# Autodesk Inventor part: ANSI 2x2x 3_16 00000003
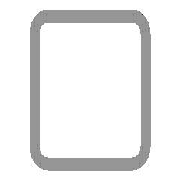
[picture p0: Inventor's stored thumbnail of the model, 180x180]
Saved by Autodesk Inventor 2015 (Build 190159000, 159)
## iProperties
_FrameMemberDoc: Frame Member File
_Version: 15.0.0
_CCFamilyMember: 1
_CCFamilyDisplayName: ANSI AISC (Square) - Tube
Created: 2007-02
Part Number: ANSI 2x2x 3_16 00000003
Material: Steel
Document SubType Name: Modeling
Standard: AISC
Designer: Autodesk, Inc.
Size Designation: 2x2x3/16
Stock Number: 2x2x 3/16
Density: 7.85 g/cm^3
Description: Tube
Standards Organization: ANSI
Language: en-US
Categories: <MemberInstance><Categories><Category DisplayName="Structural Shapes" InternalName="089c4875-fa83-4c05-b084-43b9cc11f5ed" Mnemonic="GRDR"><CategoryParameter Dis
Mass: 3346.04 g
Surface Area: 1806.39 cm^2
Volume: 426.248 cm^3
Appearance: Steel
IsCustomPart: 1
G_L: 20.500 in
G_W: 2.000 in
G_H: 2.000 in
+D0CDFDCA-4112-49B6-A064-F741B9AF15A3+CUTDETAIL1: Cut
+A485B58D-E367-4ED6-8CC1-ECB7B964D423+CUTDETAIL2: Cut
Author: Autodesk, Inc.
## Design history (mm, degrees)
node "Start plane"
node "End plane"
sketch "Sketch"
  geometry: L1 (-25.4, -15.875)-(-25.4, 15.875); L2 (-15.875, 25.4)-(15.875, 25.4); L3 (25.4, 15.875)-(25.4, -15.875); L4 (15.875, -25.4)-(-15.875, -25.4); L5 (-15.875, 20.637)-(15.875, 20.638); L6 (20.637, 15.875)-(20.637, -15.875); L7 (15.875, -20.637)-(-15.875, -20.638); L8 (-20.637, -15.875)-(-20.637, 15.875); L9 (0, 38.322)-(0, -38.322) reference; L10 (-38.322, 0)-(38.322, 0) reference; A1 r 9.525 centre (-15.875, -15.875) between (-25.4, -15.875) and (-15.875, -25.4); A2 r 9.525 centre (-15.875, 15.875) between (-15.875, 25.4) and (-25.4, 15.875); A3 r 9.525 centre (15.875, 15.875) between (25.4, 15.875) and (15.875, 25.4); A4 r 9.525 centre (15.875, -15.875) between (15.875, -25.4) and (25.4, -15.875); A5 r 4.762 centre (-15.875, 15.875) between (-15.875, 20.637) and (-20.637, 15.875); A6 r 4.762 centre (15.875, 15.875) between (20.637, 15.875) and (15.875, 20.638); A7 r 4.762 centre (15.875, -15.875) between (15.875, -20.637) and (20.637, -15.875); A8 r 4.762 centre (-15.875, -15.875) between (-20.637, -15.875) and (-15.875, -20.638)
  constraints: 16 end point, 16 point on circle, 8 centre point, 8 tangent, 4 parallel, 3 equal radius, 2 perpendicular, 7 other
  dimensions: "d10" = 50.8 distance between parallel lines of L2 L4 (= G_H); "d11" = 50.8 distance between parallel lines of L1 L3 (= G_W); "d12" = 4.7625 distance between parallel lines of L3 L6 (= G_T); "d15" = 25.4 distance between parallel lines of L2 L10 (= 0.5 x d10); "d16" = 25.4 distance between parallel lines of L9 L3 (= 0.5 x d11); "d17" = 9.525 radius of A1 (= G_IR)
extrude "Body" new body sketch "Sketch" stored distance "d3" = 520.7 (= G_L); taper "d4" = 0 deg
node "Driven Length"
  sketch "Sketch3"
    geometry: L1 (0, 0)-(10, 0) reference
    constraints: 2 end point, 1 horizontal
  workplane "Work Plane5"
  sketch "Sketch4"
    geometry: L1 (-2, -6.35)-(12, -6.35) reference; L2 (-2, 514.35)-(12, 514.35) reference
    dimensions: "d19" = 520.7 distance between parallel lines of L1 L2 (derived)
workplane "Work Plane3"
split "Split1"
workplane "Work Plane4"
split "Split2"
body "Solid1"
other parameters: "G_W" = 50.8 [user parameter; used in 1 equation term], "G_H" = 50.8 [user parameter; used in 1 equation term], "G_T" = 4.7625 [user parameter; used in 1 equation term], "G_IR" = 9.525 [user parameter; used in 1 equation term], "G_L" = 520.7 (= d19) [user parameter; used in 1 equation term], "G_OFFSET_START" = 6.35 [user parameter; used in 1 equation term], "G_OFFSET_END" = 6.35 [user parameter; used in 1 equation term], "d13" = -6.35 (= -G_OFFSET_START), "d14" = 514.35 (= G_OFFSET_END + B_L), "B_L" = 508 [user parameter; used in 1 equation term], "d18" = 90 deg
